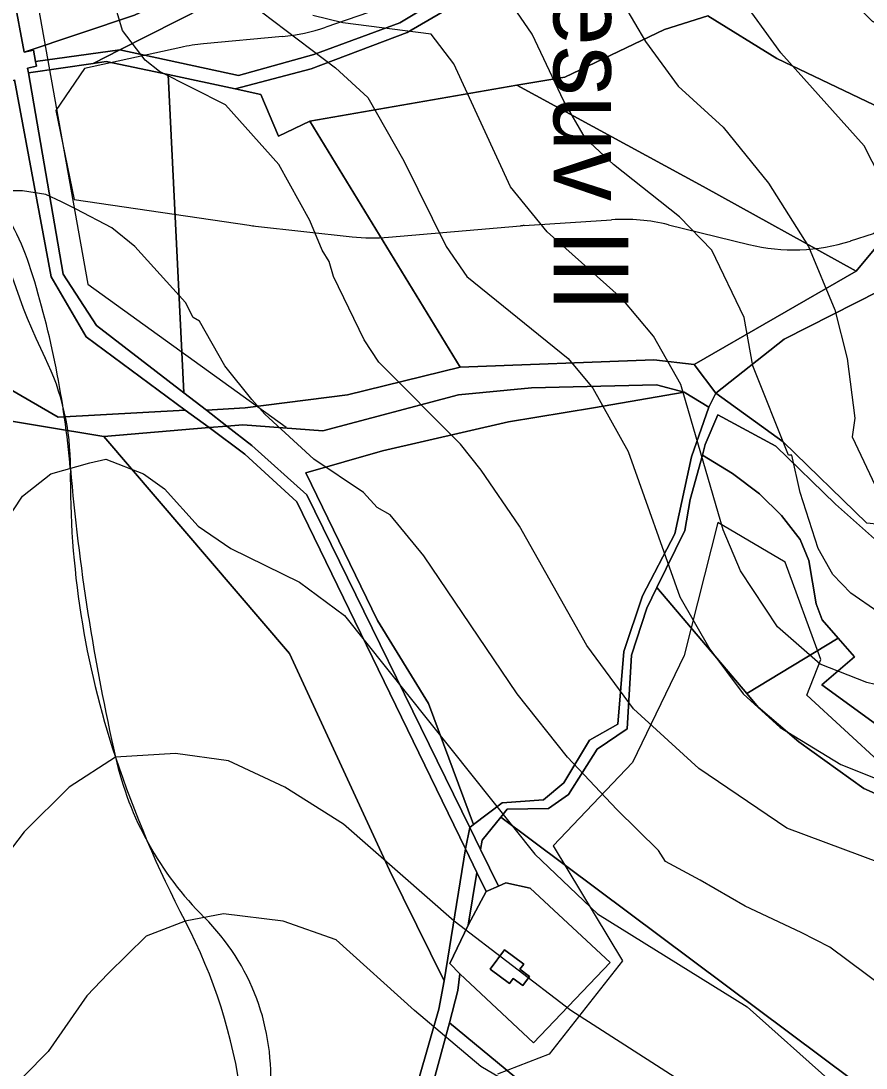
# Model space of a CAD drawing. Extents: x -510989 to -501240, y -1184665 to -1176098.
# Drawn here: x -504051.9 to -503825.1, y -1182172.4 to -1181891.5 of the extents above; entities that cross this region are included whole.
import ezdxf

# ---------------------------------------------------------------- set-up
doc = ezdxf.new("R2010")
doc.units = 0
for name, color, linetype in [('lesni_pozemek', 7, 'Continuous'), ('NAVRH_interakcni_prvky', 7, 'Continuous'), ('NAVRH_rozvodnice', 7, 'Continuous'), ('orna_puda', 7, 'Continuous'), ('ostatni_plocha_x_jina_plocha', 7, 'Continuous'), ('ostatni_plocha_x_neplodna_puda', 7, 'Continuous'), ('ostatni_plocha_x_ostatni_komunikace', 7, 'Continuous'), ('STAV_erozne_ohrozene_plochy', 7, 'Continuous'), ('STAV_povodi', 7, 'Continuous'), ('STAV_systematicke_odvodneni', 7, 'Continuous'), ('STAV_zaplavove_uzemi', 7, 'Continuous'), ('trvaly_travni_porost', 7, 'Continuous'), ('vrstevnice_01', 7, 'Continuous'), ('vrstevnice_02', 7, 'Continuous'), ('zastavena_plocha_a_nadvori', 7, 'Continuous')]:
    doc.layers.add(name, color=color, linetype=linetype)

msp = doc.modelspace()

# ---------------------------------------------------------------- linework, layer by layer
at = {"layer": 'lesni_pozemek'}
for points in [[(-503881.35, -1181989.05), (-503873.91, -1181991.08), (-503898.28, -1181995.25), (-503921.05, -1181999.05), (-503954.88, -1182006.83), (-503975.41, -1182012.73), (-503956.18, -1182052.3), (-503942.51, -1182074.56), (-503930.41, -1182107.03), (-503931.44, -1182107.84), (-503975.2, -1182018.61), (-503989.92, -1182005.33), (-503996.6, -1182000.17), (-503992.33, -1181999.81), (-503970.86, -1182001.42), (-503934.46, -1181991.81), (-503914.84, -1181989.9)], [(-503867.33, -1181995.07), (-503871.96, -1182008.42), (-503876.44, -1182029.06), (-503885.1, -1182045.66), (-503890.11, -1182060.62), (-503891.68, -1182080.12), (-503899.29, -1182084.47), (-503906.16, -1182095.86), (-503911.67, -1182100.45), (-503922.79, -1182101.2), (-503930.41, -1182107.03), (-503942.51, -1182074.56), (-503956.18, -1182052.3), (-503975.41, -1182012.73), (-503954.88, -1182006.83), (-503921.05, -1181999.05), (-503898.28, -1181995.25), (-503873.91, -1181991.08)], [(-504029.66, -1182002.93), (-504001.4, -1182000.58), (-503991.78, -1182007.68), (-503977.86, -1182020.51), (-503932.62, -1182113.62), (-503938.34, -1182149.04), (-503953.01, -1182119.29), (-503979.79, -1182061.16)]]:
    msp.add_lwpolyline(points, close=True, dxfattribs=at)
msp.add_lwpolyline([(-504086.38, -1182189.26), (-504088.87, -1182159.39), (-504087.48, -1182159.25), (-504086, -1182159.08), (-504088.53, -1182117.8), (-504086.76, -1182078.07), (-504081.51, -1182055.76), (-504062.62, -1181997.5), (-504029.66, -1182002.93), (-503979.79, -1182061.16), (-503953.01, -1182119.29), (-503938.34, -1182149.04), (-503939.73, -1182156.64), (-503950.47, -1182194.03)], dxfattribs=at)
at = {"layer": 'NAVRH_interakcni_prvky'}
msp.add_lwpolyline([(-504079.7, -1181588.35), (-504079.7, -1181678.45), (-504061.98, -1181805.48), (-504033.91, -1181962.05), (-503980.74, -1182000.45)], dxfattribs=at)
at = {"layer": 'NAVRH_rozvodnice'}
for centre, radius, start, end in [((-504115.92, -1181979.24), 69.98, 17.4963, 36.6198), ((-504285.91, -1182032.83), 248.21, 4.9294, 17.4963), ((-503471.51, -1181962.59), 569.2, 184.9294, 192.8314), ((-503940.47, -1182069.4), 88.24, 192.8314, 225.1863), ((-504045.24, -1182174.86), 60.42, 355.5955, 45.1863)]:
    msp.add_arc(centre, radius, start, end, dxfattribs=at)
at = {"layer": 'orna_puda'}
msp.add_lwpolyline([(-503821.52, -1181963.89), (-503796.02, -1181974.83), (-503794.92, -1181987.31), (-503800.03, -1182007.6), (-503808.7, -1182020.96), (-503816.24, -1182027.09), (-503824.94, -1182026.22), (-503847.37, -1182004.36), (-503865.39, -1181991.29), (-503847.09, -1181976.85)], close=True, dxfattribs=at)
at = {"layer": 'ostatni_plocha_x_jina_plocha'}
for points in [[(-503923.72, -1182123.59), (-503921.73, -1182122.73), (-503915.24, -1182124.11), (-503893.75, -1182144.09), (-503914.38, -1182165.65), (-503934.15, -1182147.13), (-503936.78, -1182144.38), (-503931.84, -1182134.03), (-503927.06, -1182125.05)], [(-503922.12, -1182140.67), (-503925.96, -1182145.83), (-503920.77, -1182149.68), (-503919.79, -1182148.37), (-503917.23, -1182150.27), (-503915.4, -1182147.82), (-503918, -1182145.89), (-503916.9, -1182144.52)]]:
    msp.add_lwpolyline(points, close=True, dxfattribs=at)
at = {"layer": 'ostatni_plocha_x_neplodna_puda'}
msp.add_lwpolyline([(-503818.64, -1182082.93), (-503836.95, -1182069.59), (-503828.21, -1182062.06), (-503832.56, -1182057.06), (-503836.85, -1182052.15), (-503838.53, -1182047.85), (-503840.46, -1182036.21), (-503842.77, -1182030.57), (-503847.82, -1182024.14), (-503853.69, -1182018.33), (-503860.99, -1182012.84), (-503869.02, -1182007.97), (-503868.24, -1182005.12), (-503864.91, -1181997.18), (-503849.34, -1182005.52), (-503833.27, -1182021.1), (-503820.43, -1182032.56)], dxfattribs=at)
at = {"layer": 'ostatni_plocha_x_ostatni_komunikace'}
for points in [[(-504053.77, -1181884.91), (-504050.98, -1181899.82), (-504048.54, -1181899.3), (-504047.92, -1181902.32), (-504047.65, -1181903.61), (-504050.1, -1181904.1), (-504049.88, -1181905.36), (-504040.52, -1181959.43), (-504031.55, -1181973.18), (-504008.2, -1181991.23), (-504002.12, -1181995.92), (-503996.6, -1182000.17), (-504001.4, -1182000.58), (-504007.77, -1181995.87), (-504034.34, -1181976.25), (-504043.72, -1181960.14), (-504053.57, -1181907.3)], [(-503820.43, -1182032.56), (-503833.27, -1182021.1), (-503849.34, -1182005.52), (-503864.91, -1181997.18), (-503868.24, -1182005.12), (-503869.02, -1182007.97), (-503872.27, -1182019.83), (-503873.71, -1182028.19), (-503881.23, -1182043.49), (-503883.95, -1182049.01), (-503888.07, -1182061.62), (-503889.23, -1182081.39), (-503897.24, -1182086.85), (-503904.98, -1182099.05), (-503910.28, -1182102.74), (-503921.38, -1182102.94), (-503923.1, -1182105.13), (-503928.15, -1182111.25), (-503928.56, -1182113.73), (-503931.44, -1182107.84), (-503930.41, -1182107.03), (-503922.79, -1182101.2), (-503911.67, -1182100.45), (-503906.16, -1182095.86), (-503899.29, -1182084.47), (-503891.68, -1182080.12), (-503890.11, -1182060.62), (-503885.1, -1182045.66), (-503876.44, -1182029.06), (-503871.96, -1182008.42), (-503867.33, -1181995.07), (-503865.39, -1181991.29), (-503847.37, -1182004.36), (-503824.94, -1182026.22)]]:
    msp.add_lwpolyline(points, dxfattribs=at)
for points in [[(-504001.4, -1182000.58), (-503996.6, -1182000.17), (-503989.92, -1182005.33), (-503975.2, -1182018.61), (-503931.44, -1182107.84), (-503932.62, -1182113.62), (-503977.86, -1182020.51), (-503991.78, -1182007.68)], [(-503932.62, -1182113.62), (-503931.44, -1182107.84), (-503928.56, -1182113.73), (-503923.72, -1182123.59), (-503927.06, -1182125.05), (-503929.56, -1182119.92)], [(-503929.56, -1182119.92), (-503931.84, -1182134.03), (-503936.78, -1182144.38), (-503934.15, -1182147.13), (-503934.67, -1182151.57), (-503936.91, -1182160.27), (-503946.42, -1182195.4), (-503953.08, -1182206.13), (-503951.64, -1182212.9), (-503955.02, -1182213.6), (-503957.21, -1182206.01), (-503950.47, -1182194.03), (-503939.73, -1182156.64), (-503938.34, -1182149.04), (-503932.62, -1182113.62)], [(-503927.06, -1182125.05), (-503931.84, -1182134.03), (-503929.56, -1182119.92)]]:
    msp.add_lwpolyline(points, close=True, dxfattribs=at)
at = {"layer": 'STAV_erozne_ohrozene_plochy'}
for p, q in [((-503938.22, -1181882.13), (-503970.02, -1181893.11)), ((-503981.71, -1181895.63), (-504002.88, -1181897.6)), ((-503988.9, -1181946.49), (-503963.03, -1181949.36)), ((-503953.21, -1181949.49), (-503917.82, -1181946.44)), ((-503916.85, -1181946.36), (-503893.42, -1181944.8)), ((-503878.16, -1181946.13), (-503856.53, -1181951.45))]:
    msp.add_line(p, q, dxfattribs=at)
for points in [[(-503829.3, -1181950.5), (-503823.08, -1181948.5), (-503799.17, -1181921.79), (-503799.17, -1181905.62), (-503816.03, -1181891.46)], [(-504008.97, -1181898.55), (-504034.79, -1181904.21), (-504042.53, -1181915.46)], [(-504042.53, -1181915.46), (-504037.6, -1181939.36), (-503990.65, -1181946.27)]]:
    msp.add_lwpolyline(points, dxfattribs=at)
for centre, start, end in [((-503986.34, -1181845.84), 275.3123, 289.0503), ((-503998.25, -1181947.38), 95.3123, 102.3757), ((-503983.38, -1181896.8), 261.6376, 263.6625), ((-503913.52, -1181996.25), 93.8125, 94.925), ((-503890.09, -1181994.69), 76.1906, 93.8125), ((-503957.51, -1181899.67), 263.6625, 274.925), ((-503844.59, -1181902.9), 256.1906, 287.8119)]:
    msp.add_arc(centre, 50, start, end, dxfattribs=at)
at = {"layer": 'STAV_povodi'}
for centre, radius, start, end in [((-503901.81, -1181910.84), 160.17, 189.5822, 206.335), ((-504103.7, -1182010.77), 65.1, 359.3595, 26.335), ((-503801.51, -1182014.15), 237.11, 179.3595, 198.4013), ((-503744.38, -1181995.14), 297.33, 198.4013, 207.6233), ((-504135.94, -1182200.05), 144.61, 7.7698, 27.6233)]:
    msp.add_arc(centre, radius, start, end, dxfattribs=at)
at = {"layer": 'STAV_systematicke_odvodneni'}
for p, q in [((-503864.91, -1182026.05), (-503873.95, -1182061.71)), ((-503846.82, -1182036.69), (-503864.91, -1182026.05)), ((-503837.25, -1182062.77), (-503846.82, -1182036.69)), ((-503873.95, -1182061.71), (-503887.79, -1182090.45)), ((-503840.97, -1182072.35), (-503837.25, -1182062.77)), ((-503820.76, -1182090.98), (-503840.97, -1182072.35)), ((-503887.79, -1182090.45), (-503909.07, -1182112.8)), ((-503909.07, -1182112.8), (-503890.45, -1182143.67)), ((-503890.45, -1182143.67), (-503910.13, -1182168.68)), ((-503910.13, -1182168.68), (-503923.96, -1182174))]:
    msp.add_line(p, q, dxfattribs=at)
at = {"layer": 'STAV_zaplavove_uzemi'}
msp.add_spline([(-502250.32, -1184002.61), (-502355.07, -1183875.41), (-502442.37, -1183790.61), (-502477.29, -1183700.82), (-502532.16, -1183578.61), (-502567.08, -1183448.91), (-502626.05, -1183402.34), (-502705.41, -1183380.59), (-502814.2, -1183349.87), (-502882.03, -1183297.39), (-502931.95, -1183237.24), (-503042.02, -1183107.97), (-503139.64, -1183018.94), (-503222.14, -1182957.59), (-503308.56, -1182839.96), (-503316.24, -1182784.92), (-503330.32, -1182756.77), (-503348.24, -1182719.65), (-503334.16, -1182651.82), (-503323.92, -1182595.5), (-503313.68, -1182526.39), (-503294.1, -1182480.5), (-503251.86, -1182396.03), (-503229.34, -1182314.37), (-503216.1, -1182227.15), (-503242.43, -1182174.5), (-503271.86, -1182129.59), (-503287.34, -1182081.58), (-503343.88, -1182028.1), (-503361.79, -1182008.91), (-503396.35, -1181952.59), (-503442.43, -1181933.39), (-503497.46, -1181888.6), (-503525.62, -1181860.44), (-503528.18, -1181837.4), (-503548.66, -1181767.01), (-503558.9, -1181729.89), (-503576.82, -1181682.53), (-503578.1, -1181621.1), (-503567.86, -1181572.46), (-503552.5, -1181536.63), (-503538.04, -1181458.36), (-503518.33, -1181411.9), (-503509.88, -1181341.51), (-503497.21, -1181207.63), (-503499.77, -1181097.56), (-503498.02, -1181031.35), (-503510.82, -1180970.85), (-503549.22, -1180952.23), (-503571.32, -1180940.6), (-503605.07, -1180937.11), (-503651.61, -1180939.44), (-503671.39, -1180917.33), (-503679.53, -1180892.89), (-503713.27, -1180871.95), (-503727.24, -1180859.15), (-503734.22, -1180833.55), (-503728.4, -1180799.81), (-503741.2, -1180770.72), (-503722.82, -1180725.17), (-503721.54, -1180703.41), (-503731.78, -1180697.01), (-503767.61, -1180699.57), (-503790.65, -1180697.01), (-503817.53, -1180697.01), (-503861.04, -1180686.77), (-503889.2, -1180675.25), (-503900.72, -1180668.85), (-503953.2, -1180679.09), (-503997.99, -1180697.01), (-504063.27, -1180722.61), (-504109.34, -1180749.49), (-504142.62, -1180776.36), (-504177.18, -1180796.84), (-504211.73, -1180817.32), (-504414.98, -1180961.5), (-504472.7, -1180998.11), (-504544.51, -1181068.5), (-504600.82, -1181143.12), (-504621.94, -1181196.62), (-504641.65, -1181267.01), (-504660.25, -1181350.62), (-504634.7, -1181398.32), (-504617.66, -1181447.72), (-504600.62, -1181492.01), (-504587, -1181548.23), (-504592.11, -1181628.29), (-504569.96, -1181682.81), (-504568.26, -1181664.07), (-504554.63, -1181621.48), (-504547.82, -1181597.63)], degree=3, dxfattribs=at)
at = {"layer": 'trvaly_travni_porost'}
for points in [[(-503937.94, -1181835.43), (-503928.5, -1181845.26), (-503953.15, -1181858.08), (-504021.42, -1181889.93), (-504050.98, -1181899.82), (-504053.77, -1181884.91), (-504028.74, -1181874.82), (-503999.37, -1181862.56)], [(-503928.5, -1181845.26), (-503924.39, -1181848.09), (-504025.34, -1181899.24), (-504047.92, -1181902.32), (-504048.54, -1181899.3), (-504050.98, -1181899.82), (-504021.42, -1181889.93), (-503953.15, -1181858.08)], [(-503924.39, -1181848.09), (-503904.08, -1181862.78), (-503895.87, -1181866.04), (-503921.49, -1181874.68), (-503950.18, -1181891.99), (-503973.27, -1181900.5), (-503993.47, -1181906.08), (-504025.34, -1181899.24)], [(-503867.78, -1181862.89), (-503840.41, -1181868.88), (-503820.87, -1181888.94), (-503799.76, -1181898.9), (-503800.16, -1181902.44), (-503823.49, -1181891.48), (-503842.31, -1181872.52), (-503869.19, -1181865.9), (-503882.82, -1181865.56), (-503920.1, -1181878.14), (-503948.2, -1181894.55), (-503974.03, -1181904.3), (-503994.41, -1181909.66), (-504012.33, -1181905.82), (-504028.96, -1181902.35), (-504032.45, -1181902.85), (-504025.34, -1181899.24), (-503993.47, -1181906.08), (-503973.27, -1181900.5), (-503950.18, -1181891.99), (-503921.49, -1181874.68), (-503895.87, -1181866.04), (-503889.65, -1181864.08), (-503884.6, -1181862.2)], [(-503882.82, -1181865.56), (-503869.19, -1181865.9), (-503842.31, -1181872.52), (-503823.49, -1181891.48), (-503800.16, -1181902.44), (-503802.61, -1181924.03), (-503820.94, -1181914.94), (-503849.06, -1181901.55), (-503867.54, -1181890.05), (-503879.17, -1181893.76), (-503905.94, -1181906.58), (-503918.79, -1181908.72), (-503974.32, -1181918.33), (-503982.78, -1181922.41), (-503987.46, -1181911.16), (-503994.41, -1181909.66), (-503974.03, -1181904.3), (-503948.2, -1181894.55), (-503920.1, -1181878.14)], [(-503867.54, -1181890.05), (-503849.06, -1181901.55), (-503820.94, -1181914.94), (-503802.61, -1181924.03), (-503804.85, -1181933.72), (-503811.49, -1181939.02), (-503827.79, -1181958.63), (-503868.78, -1181935.86), (-503918.79, -1181908.72), (-503905.94, -1181906.58), (-503879.17, -1181893.76)], [(-504025.34, -1181899.24), (-504032.45, -1181902.85), (-504049.88, -1181905.36), (-504050.1, -1181904.1), (-504047.65, -1181903.61), (-504047.92, -1181902.32)], [(-504028.96, -1181902.35), (-504012.33, -1181905.82), (-504008.2, -1181991.23), (-504031.55, -1181973.18), (-504040.52, -1181959.43), (-504049.88, -1181905.36), (-504032.45, -1181902.85)], [(-504066.47, -1181913.32), (-504053.57, -1181907.3), (-504043.72, -1181960.14), (-504034.34, -1181976.25), (-504007.77, -1181995.87), (-504041.84, -1181997.75), (-504054.68, -1181990.33), (-504060.33, -1181975.34), (-504065.1, -1181944.19)], [(-503994.41, -1181909.66), (-503987.46, -1181911.16), (-503982.78, -1181922.41), (-503974.32, -1181918.33), (-503933.99, -1181984.36), (-503964.23, -1181991.74), (-503991.72, -1181995.3), (-504002.12, -1181995.92), (-504008.2, -1181991.23), (-504012.33, -1181905.82)], [(-503918.79, -1181908.72), (-503868.78, -1181935.86), (-503827.79, -1181958.63), (-503871.27, -1181983.68), (-503882.05, -1181982.42), (-503933.99, -1181984.36), (-503974.32, -1181918.33)], [(-503808.27, -1181943.38), (-503813.41, -1181947.73), (-503822.44, -1181959.84), (-503821.52, -1181963.89), (-503847.09, -1181976.85), (-503865.39, -1181991.29), (-503871.27, -1181983.68), (-503827.79, -1181958.63), (-503811.49, -1181939.02)], [(-504060.33, -1181975.34), (-504054.68, -1181990.33), (-504041.84, -1181997.75), (-504007.77, -1181995.87), (-504001.4, -1182000.58), (-504029.66, -1182002.93), (-504062.62, -1181997.5), (-504060.03, -1181988.51)], [(-503882.05, -1181982.42), (-503871.27, -1181983.68), (-503865.39, -1181991.29), (-503867.33, -1181995.07), (-503873.91, -1181991.08), (-503881.35, -1181989.05), (-503914.84, -1181989.9), (-503934.46, -1181991.81), (-503970.86, -1182001.42), (-503992.33, -1181999.81), (-503996.6, -1182000.17), (-504002.12, -1181995.92), (-503991.72, -1181995.3), (-503964.23, -1181991.74), (-503933.99, -1181984.36)], [(-503869.02, -1182007.97), (-503860.99, -1182012.84), (-503853.69, -1182018.33), (-503847.82, -1182024.14), (-503842.77, -1182030.57), (-503840.46, -1182036.21), (-503838.53, -1182047.85), (-503836.85, -1182052.15), (-503832.56, -1182057.06), (-503857.1, -1182071.95), (-503881.23, -1182043.49), (-503873.71, -1182028.19), (-503872.27, -1182019.83)], [(-503881.23, -1182043.49), (-503857.1, -1182071.95), (-503854.02, -1182075.59), (-503843.17, -1182084.88), (-503825.7, -1182097.38), (-503820.3, -1182099.84), (-503731.52, -1182142.72), (-503775.54, -1182186.03), (-503794.23, -1182201.42), (-503923.1, -1182105.13), (-503921.38, -1182102.94), (-503910.28, -1182102.74), (-503904.98, -1182099.05), (-503897.24, -1182086.85), (-503889.23, -1182081.39), (-503888.07, -1182061.62), (-503883.95, -1182049.01)], [(-503832.56, -1182057.06), (-503828.21, -1182062.06), (-503836.95, -1182069.59), (-503818.64, -1182082.93), (-503813.29, -1182086.82), (-503820.3, -1182099.84), (-503825.7, -1182097.38), (-503843.17, -1182084.88), (-503854.02, -1182075.59), (-503857.1, -1182071.95)], [(-503923.1, -1182105.13), (-503794.23, -1182201.42), (-503807.14, -1182213.56), (-503838.96, -1182241.23), (-503936.91, -1182160.27), (-503934.67, -1182151.57), (-503934.15, -1182147.13), (-503914.38, -1182165.65), (-503893.75, -1182144.09), (-503915.24, -1182124.11), (-503921.73, -1182122.73), (-503923.72, -1182123.59), (-503928.56, -1182113.73), (-503928.15, -1182111.25)], [(-503946.42, -1182195.4), (-503936.91, -1182160.27), (-503838.96, -1182241.23), (-503845.1, -1182246.6), (-503878.44, -1182275.73), (-503950.42, -1182216.86), (-503951.64, -1182212.9), (-503953.08, -1182206.13)]]:
    msp.add_lwpolyline(points, close=True, dxfattribs=at)
at = {"layer": 'vrstevnice_01'}
for points in [[(-503812, -1181981), (-503811.69, -1181969), (-503816.91, -1181942), (-503825.59, -1181925), (-503848, -1181900), (-503859.5, -1181884)], [(-503987.31, -1181889), (-503967.5, -1181904), (-503958.81, -1181912), (-503949.09, -1181929), (-503937.81, -1181952), (-503932.19, -1181960), (-503905, -1181982), (-503898.41, -1181990), (-503888.91, -1182007), (-503875.09, -1182046), (-503867, -1182060), (-503858.09, -1182072), (-503848.19, -1182081), (-503831.91, -1182091), (-503814.19, -1182098), (-503798.41, -1182101), (-503785.59, -1182107), (-503773.41, -1182114), (-503748.41, -1182137), (-503738.09, -1182144), (-503728.09, -1182154), (-503713.41, -1182178)], [(-503756.91, -1182062), (-503770.41, -1182055), (-503771, -1182055), (-503796.5, -1182057), (-503809, -1182055), (-503822, -1182050), (-503829.19, -1182045), (-503834, -1182040), (-503838, -1182033), (-503842.81, -1182018), (-503845, -1182008), (-503845.91, -1182008), (-503855.5, -1181984), (-503857.81, -1181971), (-503866.5, -1181953), (-503875.19, -1181944), (-503892.91, -1181930), (-503900.41, -1181923), (-503906.19, -1181913), (-503914.69, -1181895), (-503918.81, -1181889)], [(-503820.09, -1182151), (-503834.81, -1182140), (-503842.5, -1182136), (-503857.59, -1182129), (-503869.59, -1182122), (-503878.91, -1182117), (-503880.81, -1182114), (-503892, -1182103), (-503905.19, -1182089), (-503918.69, -1182072), (-503943.81, -1182035), (-503952.81, -1182024), (-503956.31, -1182022), (-503959.91, -1182018), (-503973.31, -1182009), (-503986.41, -1181997), (-503989.91, -1181993), (-503997.19, -1181984), (-504004, -1181972), (-504005.69, -1181971), (-504007.69, -1181967), (-504021.31, -1181952), (-504027.5, -1181947), (-504037.09, -1181942), (-504041, -1181940), (-504045.19, -1181938), (-504051.41, -1181937), (-504055.5, -1181937)], [(-503871.59, -1182178), (-503904.31, -1182157), (-503935.59, -1182133), (-503965.31, -1182107), (-503981.09, -1182097), (-503996.19, -1182090), (-504010.41, -1182088), (-504026.5, -1182089), (-504038.91, -1182097), (-504051, -1182109), (-504089.81, -1182160), (-504096.41, -1182170), (-504105.69, -1182189)]]:
    msp.add_lwpolyline(points, dxfattribs=at)
at = {"layer": 'vrstevnice_02'}
for points in [[(-503887.5, -1182076), (-503900, -1182059), (-503918.09, -1182027), (-503928.41, -1182012), (-503933.91, -1182005), (-503955.81, -1181983), (-503959.81, -1181977), (-503968, -1181960), (-503969.19, -1181956), (-503971, -1181953), (-503974.31, -1181945), (-503982.69, -1181930), (-503997, -1181914), (-504014.69, -1181905), (-504018.5, -1181902), (-504024.59, -1181894), (-504028.5, -1181881)], [(-503890.19, -1181887), (-503884.31, -1181897), (-503875.5, -1181909), (-503863.41, -1181920), (-503851.31, -1181935), (-503840.59, -1181952), (-503833.5, -1181969), (-503830.19, -1181982), (-503828.09, -1181998), (-503828.81, -1182003), (-503820.31, -1182021)], [(-503677.69, -1182183), (-503690.69, -1182155), (-503700.69, -1182137), (-503711.09, -1182127), (-503743, -1182105), (-503765.19, -1182083), (-503783.69, -1182072), (-503798.31, -1182066), (-503820.41, -1182070), (-503824.91, -1182069), (-503837.41, -1182064), (-503848.91, -1182054), (-503858.81, -1182039), (-503863.41, -1182028), (-503874.81, -1181989), (-503882.19, -1181976), (-503890.59, -1181966), (-503910.69, -1181948), (-503920.5, -1181936), (-503935.69, -1181903), (-503941.81, -1181895), (-503965.5, -1181892), (-503973.59, -1181890)], [(-504137.19, -1182192), (-504124.31, -1182155), (-504111, -1182129), (-504078, -1182068), (-504063.41, -1182037), (-504051.41, -1182019), (-504043.81, -1182013), (-504033.41, -1182010), (-504029.09, -1182009), (-504019, -1182013), (-504013.31, -1182017), (-504004.31, -1182027), (-503995.59, -1182033), (-503977.09, -1182042), (-503965.09, -1182051), (-503914, -1182115), (-503897.19, -1182131), (-503857, -1182156), (-503834.59, -1182176)], [(-503745.69, -1182173), (-503758.31, -1182158), (-503783.41, -1182141), (-503790.91, -1182133), (-503806.31, -1182123), (-503846.41, -1182108), (-503870, -1182092), (-503887.5, -1182076)], [(-503901.31, -1182188), (-503928.5, -1182172), (-503946.31, -1182157), (-503967.31, -1182138), (-503981.5, -1182133), (-503997.5, -1182131), (-504007.81, -1182133), (-504018.31, -1182137), (-504028.5, -1182147), (-504034.19, -1182153), (-504044.59, -1182168), (-504070.31, -1182194)]]:
    msp.add_lwpolyline(points, dxfattribs=at)
at = {"layer": 'zastavena_plocha_a_nadvori'}
msp.add_lwpolyline([(-503922.12, -1182140.67), (-503916.9, -1182144.52), (-503918, -1182145.89), (-503915.4, -1182147.82), (-503917.23, -1182150.27), (-503919.79, -1182148.37), (-503920.77, -1182149.68), (-503925.96, -1182145.83)], close=True, dxfattribs=at)

# ---------------------------------------------------------------- texts
at = {"layer": 'STAV_erozne_ohrozene_plochy'}
msp.add_text('Sesuv III', height=20, rotation=270, dxfattribs=at).set_placement((-503908.94, -1181865.44))

doc.saveas('drawing.dxf')
